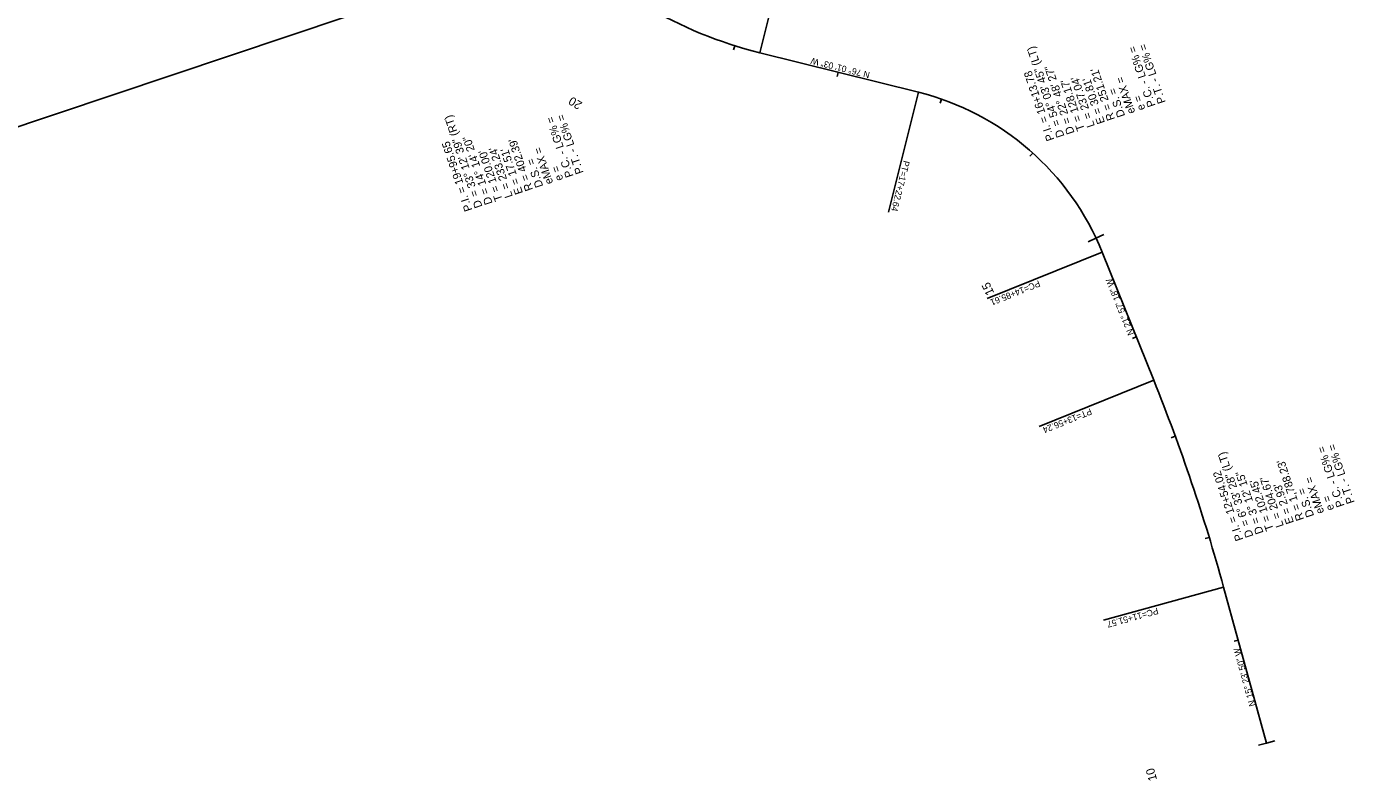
# Model space of a CAD drawing. Extents: x 1528853 to 1624411, y 1119753 to 1162242.
# Drawn here: x 1529554 to 1530799, y 1158486 to 1159193 of the extents above; entities that cross this region are included whole.
import ezdxf

# ---------------------------------------------------------------- set-up
doc = ezdxf.new("R2010")
doc.units = 0
for name, color, linetype in [('RD_HC_Cl', 7, 'Continuous'), ('RD_HC_Data', 7, 'Continuous'), ('RD_HC_Data_Tic', 7, 'Continuous'), ('RD_HC_TX_Sta50', 7, 'Continuous'), ('RD_SHT_ShtClip', 7, 'Continuous')]:
    doc.layers.add(name, color=color, linetype=linetype)

msp = doc.modelspace()

# ---------------------------------------------------------------- linework, layer by layer
at = {"layer": 'RD_HC_Cl'}
for p, q in [((1530389.9, 1159131.1), (1530241.4, 1159168.1)), ((1530610.5, 1158861.3), (1530562.2, 1158981.3)), ((1530716.3, 1158521.4), (1530676, 1158667.5))]:
    msp.add_line(p, q, dxfattribs=at)
for centre, radius, start, end in [((1530338.6, 1159558.6), 402.4, 222.8065, 256.0174), ((1530329.2, 1158887.4), 251.2, 21.955, 76.0174), ((1528952, 1158192.7), 1788.2, 15.3973, 21.955)]:
    msp.add_arc(centre, radius, start, end, dxfattribs=at)
at = {"layer": 'RD_HC_Data'}
for p, q in [((1530241.4, 1159168.1), (1530269.6, 1159281.3)), ((1530389.9, 1159131.1), (1530361.9, 1159018.9)), ((1530562.2, 1158981.3), (1530454.5, 1158937.9)), ((1530610.5, 1158861.3), (1530503.3, 1158818.1)), ((1530676, 1158667.5), (1530563.3, 1158636.5))]:
    msp.add_line(p, q, dxfattribs=at)
at = {"layer": 'RD_HC_Data_Tic'}
for p, q in [((1530218, 1159174.7), (1530216.8, 1159170.9)), ((1530314.8, 1159149.8), (1530313.8, 1159145.9)), ((1530411.6, 1159124.7), (1530410.3, 1159120.9)), ((1530497.1, 1159074.2), (1530494.5, 1159071.2)), ((1530556.4, 1158994.5), (1530549.2, 1158991.1)), ((1530556.4, 1158994.5), (1530563.7, 1158997.9)), ((1530594.2, 1158901.9), (1530590.5, 1158900.4)), ((1530630.7, 1158808.8), (1530627, 1158807.4)), ((1530662.6, 1158714), (1530658.7, 1158712.9)), ((1530689.7, 1158617.8), (1530685.9, 1158616.7)), ((1530716.3, 1158521.4), (1530708.6, 1158519.3)), ((1530716.3, 1158521.4), (1530724, 1158523.5))]:
    msp.add_line(p, q, dxfattribs=at)
at = {"layer": 'RD_SHT_ShtClip'}
msp.add_line((1530516.2, 1159424.4), (1529473.4, 1159074.4), dxfattribs=at)

# ---------------------------------------------------------------- texts
at = {"layer": 'RD_HC_Data'}
for s, height, rotation, p in [('    = 54%%d 03\' 45" (LT)', 7.5, 108.5287, (1530526.9, 1159090.1)), ('P.C. - LG% = ', 7.5, 108.5287, (1530612.3, 1159118.7)), ('P.T. - LG% = ', 7.5, 108.5287, (1530621.8, 1159121.9)), ('N 76%%d 01\' 03" W', 6, 166.0174, (1530344.9, 1159150)), ('P.I. = 16+13.78', 7.5, 108.5287, (1530517.5, 1159086.9)), ('D = 22%%d 48\' 27"', 7.5, 108.5287, (1530536.4, 1159093.2)), ("R = 251.21'", 7.5, 108.5287, (1530574.3, 1159106)), ("T = 128.17'", 7.5, 108.5287, (1530545.9, 1159096.4)), ("L = 237.04'", 7.5, 108.5287, (1530555.4, 1159099.6)), ("E = 30.81'", 7.5, 108.5287, (1530564.9, 1159102.8)), ('eMAX = ', 7.5, 108.5287, (1530593.3, 1159112.3)), ('D.S. = ', 7.5, 108.5287, (1530583.8, 1159109.1)), ('e = ', 7.5, 108.5287, (1530602.8, 1159115.5)), ('    = 33%%d 12\' 39" (RT)', 7.5, 108.5572, (1529981.5, 1159024.1)), ('P.C. - LG% = ', 7.5, 108.5572, (1530066.8, 1159052.7)), ('P.T. - LG% = ', 7.5, 108.5572, (1530076.3, 1159055.9)), ('D = 14%%d 14\' 20"', 7.5, 108.5572, (1529991, 1159027.2)), ('D', 7.5, 108.5287, (1530526.9, 1159090.1)), ('P.I. = 19+95.65', 7.5, 108.5572, (1529972, 1159020.9)), ("T = 120.00'", 7.5, 108.5572, (1530000.4, 1159030.4)), ("L = 233.24'", 7.5, 108.5572, (1530009.9, 1159033.6)), ("E = 17.51'", 7.5, 108.5572, (1530019.4, 1159036.8)), ("R = 402.39'", 7.5, 108.5572, (1530028.9, 1159040)), ('eMAX = ', 7.5, 108.5572, (1530047.8, 1159046.3)), ('D.S. = ', 7.5, 108.5572, (1530038.4, 1159043.2)), ('e = ', 7.5, 108.5572, (1530057.3, 1159049.5)), ('PT=17+22.64', 6, 256.0174, (1530376.1, 1159067.6)), ('D', 7.5, 108.5572, (1529981.5, 1159024.1)), ('PC=14+85.61', 6, 201.955, (1530502.6, 1158955.1)), ('N 21%%d 57\' 18" W', 6, 111.955, (1530592.2, 1158904.8)), ('PT=13+56.24', 6, 201.955, (1530551, 1158835.2)), ('P.T. - LG% = ', 7.5, 108.4646, (1530798.9, 1158747)), ('    = 6%%d 33\' 28" (LT)', 7.5, 108.4646, (1530704, 1158715.3)), ('P.C. - LG% = ', 7.5, 108.4646, (1530789.4, 1158743.8)), ('P.I. = 12+54.02', 7.5, 108.4646, (1530694.6, 1158712.1)), ("R = 1,788.23'", 7.5, 108.4646, (1530751.5, 1158731.1)), ('D = 3%%d 12\' 15"', 7.5, 108.4646, (1530713.5, 1158718.5)), ("T = 102.45'", 7.5, 108.4646, (1530723, 1158721.6)), ("L = 204.67'", 7.5, 108.4646, (1530732.5, 1158724.8)), ("E = 2.93'", 7.5, 108.4646, (1530742, 1158728)), ('eMAX = ', 7.5, 108.4646, (1530770.4, 1158737.5)), ('D.S. = ', 7.5, 108.4646, (1530760.9, 1158734.3)), ('e = ', 7.5, 108.4646, (1530779.9, 1158740.6)), ('D', 7.5, 108.4646, (1530704, 1158715.3)), ('PC=11+51.57', 6, 195.3973, (1530613.9, 1158648.3)), ('N 15%%d 23\' 50" W', 6, 105.3973, (1530706, 1158556.6))]:
    msp.add_text(s, height=height, rotation=rotation, dxfattribs=at).set_placement(p)
at = {"layer": 'RD_HC_TX_Sta50'}
for s, rotation, p in [('20', 148.3114, (1530075.5, 1159121.2)), ('15', 115.2381, (1530461.2, 1158943.2)), ('10', 105.3973, (1530613.7, 1158487.1))]:
    msp.add_text(s, height=8, rotation=rotation, dxfattribs=at).set_placement(p)

doc.saveas('drawing.dxf')
